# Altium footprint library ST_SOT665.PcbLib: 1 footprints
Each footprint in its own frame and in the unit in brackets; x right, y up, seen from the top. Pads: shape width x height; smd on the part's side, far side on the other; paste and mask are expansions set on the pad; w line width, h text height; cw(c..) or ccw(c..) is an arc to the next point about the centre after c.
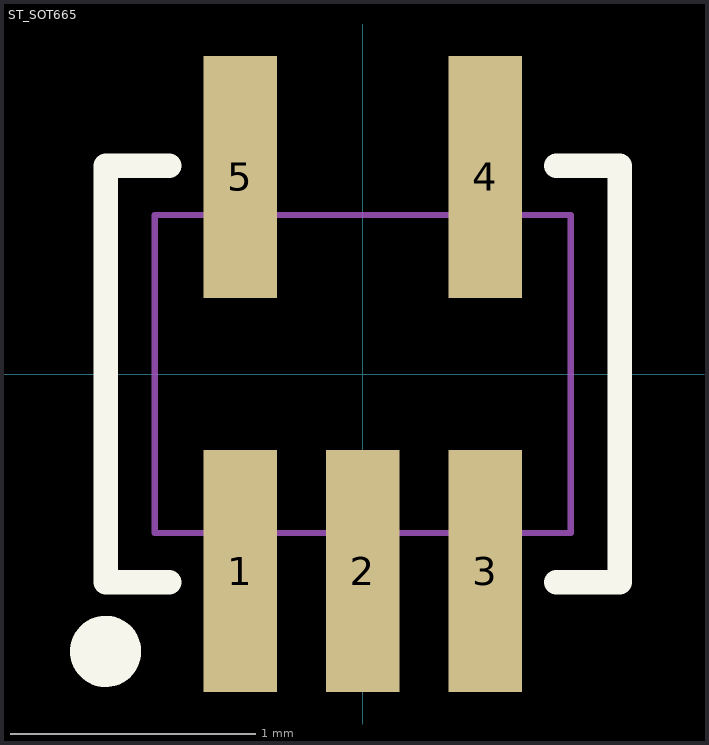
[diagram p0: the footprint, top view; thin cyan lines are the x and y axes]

## ST_SOT665 [mm] "ST_SOT665"
pads (5):
  rect 0.3x0.99 smd mask+0.025: 1(-0.5,-0.805) 2(0,-0.805) 3(0.5,-0.805) 4(0.5,0.805) 5(-0.5,0.805)
Top Overlay:
  circle w0.15: c-1.05,-1.134 r0.071
  lines w0.1: -0.79,-0.85 -1.05,-0.85 -1.05,0.85 -0.79,0.85 ; 0.79,-0.85 1.05,-0.85 1.05,0.85 0.79,0.85
Mechanical 5:
  text "5" at -0.635,1.55 h0.3
  text "4" at 0.32,1.56 h0.3
  text "3" at 0.33,-1.78 h0.3
  text "2" at -0.15,-1.802 h0.3
  text "1" at -0.589,-1.793 h0.3
Mechanical 6:
  lines w0.025: -0.85,-0.65 -0.85,0.65 0.85,0.65 0.85,-0.65 -0.85,-0.65
Mechanical 7:
  lines w0.025: -0.85,-0.65 0.85,-0.65 0.85,0.65 -0.85,0.65 -0.85,-0.65
3D body: height 0.6, standoff 0, extent -0.85,-0.65 0.85,0.65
